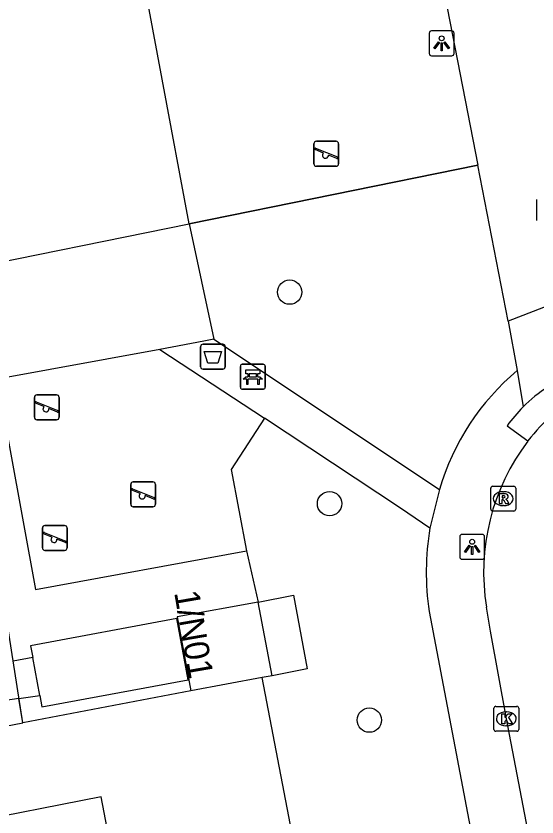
# Model space of a CAD drawing. Extents: x 159265 to 160143, y 383413 to 384319.
# Drawn here: x 159352.88 to 159373.79, y 383756.89 to 383789.05 of the extents above; entities that cross this region are included whole.
import ezdxf

# ---------------------------------------------------------------- set-up
doc = ezdxf.new("R2010")
doc.units = 0
for name, color, linetype in [('IMGEO_Afvalbak', 7, 'Continuous'), ('IMGEO_Bank', 7, 'Continuous'), ('IMGEO_Boom', 7, 'Continuous'), ('IMGEO_Groenvoorziening', 7, 'Continuous'), ('IMGEO_Haag', 7, 'Continuous'), ('IMGEO_Hek', 7, 'Continuous'), ('IMGEO_Kolk', 7, 'Continuous'), ('IMGEO_Lichtpunt', 7, 'Continuous'), ('IMGEO_Pand', 7, 'Continuous'), ('IMGEO_Pand_nummerreeks', 7, 'Continuous'), ('IMGEO_Rijbaan_lokaal_open', 7, 'Continuous'), ('IMGEO_Rioolput', 7, 'Continuous'), ('IMGEO_Speelvoorziening', 7, 'Continuous'), ('IMGEO_Voetpad_open', 7, 'Continuous')]:
    doc.layers.add(name, color=color, linetype=linetype)

msp = doc.modelspace()

# ---------------------------------------------------------------- linework, layer by layer
at = {"layer": 'IMGEO_Afvalbak'}
for p, q in [((159360.284, 383774.97), (159360.284, 383775.77)), ((159360.284, 383775.77), (159360.284, 383774.97)), ((159360.384, 383775.87), (159361.174, 383775.87)), ((159361.174, 383775.87), (159360.384, 383775.87)), ((159361.274, 383775.77), (159361.274, 383774.97)), ((159361.274, 383774.97), (159361.274, 383775.77)), ((159361.174, 383774.87), (159360.384, 383774.87)), ((159360.384, 383774.87), (159361.174, 383774.87))]:
    msp.add_line(p, q, dxfattribs=at)
msp.add_lwpolyline([(159360.427, 383775.584), (159361.131, 383775.584), (159360.982, 383775.114), (159360.576, 383775.114), (159360.427, 383775.584)], dxfattribs=at)
for centre, start, end in [((159360.384, 383775.77), 90, 180), ((159360.384, 383775.77), 90, 180), ((159361.174, 383775.77), 0, 90), ((159361.174, 383775.77), 360, 90), ((159360.384, 383774.97), 180, 270), ((159360.384, 383774.97), 180, 270), ((159361.174, 383774.97), 270, 0), ((159361.174, 383774.97), 270, 0)]:
    msp.add_arc(centre, 0.1, start, end, dxfattribs=at)
at = {"layer": 'IMGEO_Bank'}
for p, q in [((159361.883, 383774.142), (159361.883, 383774.983)), ((159361.883, 383774.983), (159361.883, 383774.142)), ((159361.958, 383775.067), (159362.799, 383775.067)), ((159362.799, 383775.067), (159361.958, 383775.067)), ((159362.883, 383774.992), (159362.883, 383774.151)), ((159362.883, 383774.151), (159362.883, 383774.992)), ((159362.58, 383774.465), (159362.187, 383774.465)), ((159362.192, 383774.573), (159362.192, 383774.679)), ((159362.236, 383774.679), (159362.236, 383774.573)), ((159362.524, 383774.685), (159362.242, 383774.685)), ((159362.242, 383774.567), (159362.524, 383774.567)), ((159362.53, 383774.573), (159362.53, 383774.679)), ((159362.574, 383774.679), (159362.574, 383774.573)), ((159362.808, 383774.067), (159361.967, 383774.067)), ((159361.967, 383774.067), (159362.808, 383774.067))]:
    msp.add_line(p, q, dxfattribs=at)
for points in [[(159362.186, 383774.685), (159362.1, 383774.685), (159362.1, 383774.846), (159362.663, 383774.846), (159362.663, 383774.685), (159362.58, 383774.685)], [(159362.13, 383774.465), (159361.988, 383774.465), (159362.1, 383774.567), (159362.186, 383774.567)], [(159362.18, 383774.458), (159362.18, 383774.251), (159362.137, 383774.251), (159362.137, 383774.458)], [(159362.58, 383774.567), (159362.663, 383774.567), (159362.775, 383774.465), (159362.636, 383774.465)], [(159362.63, 383774.458), (159362.63, 383774.251), (159362.586, 383774.251), (159362.586, 383774.458)]]:
    msp.add_lwpolyline(points, dxfattribs=at)
for centre, radius, start, end in [((159361.961, 383774.989), 0.0779, 92.4484, 184.2845), ((159361.961, 383774.989), 0.0779, 92.4484, 184.2845), ((159362.805, 383774.989), 0.0779, 2.4484, 94.2845), ((159362.805, 383774.989), 0.0779, 2.4484, 94.2845), ((159362.13, 383774.458), 0.00671, 2.8957, 87.1043), ((159362.187, 383774.458), 0.00671, 92.8957, 177.1043), ((159362.185, 383774.678), 0.00671, 2.8957, 87.1043), ((159362.185, 383774.574), 0.00671, 272.8957, 357.1043), ((159362.242, 383774.678), 0.00671, 92.8957, 177.1043), ((159362.242, 383774.574), 0.00671, 182.8957, 267.1043), ((159362.524, 383774.678), 0.00671, 2.8957, 87.1043), ((159362.524, 383774.574), 0.00671, 272.8957, 357.1043), ((159362.581, 383774.678), 0.00671, 92.8957, 177.1043), ((159362.581, 383774.574), 0.00671, 182.8957, 267.1043), ((159362.579, 383774.458), 0.00671, 2.8957, 87.1043), ((159362.636, 383774.458), 0.00671, 92.8957, 177.1043), ((159361.961, 383774.145), 0.0779, 182.4484, 274.2845), ((159361.961, 383774.145), 0.0779, 182.4484, 274.2845), ((159362.805, 383774.145), 0.0779, 272.4484, 4.2845), ((159362.805, 383774.145), 0.0779, 272.4484, 4.2845)]:
    msp.add_arc(centre, radius, start, end, dxfattribs=at)
at = {"layer": 'IMGEO_Boom'}
for centre in [(159363.859, 383777.962), (159365.461, 383769.471), (159367.059, 383760.78)]:
    msp.add_circle(centre, 0.489, dxfattribs=at)
at = {"layer": 'IMGEO_Groenvoorziening'}
for points in [[(159371.407, 383783.066), (159359.832, 383780.702)], [(159359.832, 383780.702), (159360.811, 383776.068)], [(159358.645, 383775.662), (159352.106, 383774.47), (159353.662, 383766.028), (159362.132, 383767.578)], [(159362.851, 383772.897), (159361.511, 383770.836), (159362.132, 383767.578)], [(159362.132, 383767.578), (159362.599, 383765.517)], [(159368.719, 383731.446), (159365.154, 383750), (159362.754, 383762.488)], [(159359.896, 383761.959), (159353.148, 383760.666)]]:
    msp.add_lwpolyline(points, dxfattribs=at)
at = {"layer": 'IMGEO_Haag'}
for points in [[(159353.148, 383760.666), (159352.995, 383761.644)], [(159333.621, 383756.912), (159353.148, 383760.666)]]:
    msp.add_lwpolyline(points, dxfattribs=at)
at = {"layer": 'IMGEO_Hek'}
for points in [[(159359.832, 383780.702), (159354.405, 383809.755)], [(159359.832, 383780.702), (159371.407, 383783.066)], [(159350.482, 383777.746), (159350.322, 383778.775), (159359.832, 383780.702)], [(159353.148, 383760.666), (159350.482, 383777.746)], [(159359.896, 383761.959), (159353.148, 383760.666)]]:
    msp.add_lwpolyline(points, dxfattribs=at)
at = {"layer": 'IMGEO_Kolk'}
for p, q in [((159373.785, 383780.835), (159373.785, 383781.687)), ((159372.055, 383760.407), (159372.055, 383761.259)), ((159372.13, 383761.333), (159372.982, 383761.333)), ((159373.056, 383761.259), (159373.056, 383760.407)), ((159372.543, 383761.113), (159372.568, 383761.113)), ((159372.982, 383760.333), (159372.13, 383760.333)), ((159372.566, 383760.553), (159372.541, 383760.553))]:
    msp.add_line(p, q, dxfattribs=at)
for points in [[(159373.785, 383780.835), (159373.785, 383781.687)], [(159372.055, 383760.407), (159372.055, 383761.259)], [(159372.13, 383761.333), (159372.982, 383761.333)], [(159373.056, 383761.259), (159373.056, 383760.407)], [(159372.376, 383761.033), (159372.499, 383761.033), (159372.499, 383760.882), (159372.629, 383761.033), (159372.793, 383761.033), (159372.647, 383760.882), (159372.8, 383760.633), (159372.648, 383760.633), (159372.563, 383760.797), (159372.499, 383760.73), (159372.499, 383760.633), (159372.376, 383760.633), (159372.376, 383761.033)], [(159372.982, 383760.333), (159372.13, 383760.333)]]:
    msp.add_lwpolyline(points, dxfattribs=at)
for centre, start, end in [((159372.132, 383761.257), 91.552, 178.448), ((159372.132, 383761.257), 91.552, 178.448), ((159372.98, 383761.257), 1.552, 88.448), ((159372.98, 383761.257), 1.552, 88.448), ((159372.132, 383760.409), 181.552, 268.448), ((159372.132, 383760.409), 181.552, 268.448), ((159372.98, 383760.409), 271.552, 358.448), ((159372.98, 383760.409), 271.552, 358.448)]:
    msp.add_arc(centre, 0.0765, start, end, dxfattribs=at)
for centre, major_axis, ratio, start_param, end_param in [((159372.542, 383760.833), (-0.387, 0.002), 0.722429, 4.712389, 7.853982), ((159372.567, 383760.833), (-0.39, 0.002), 0.717154, 1.570796, 4.712389)]:
    msp.add_ellipse(centre, major_axis=major_axis, ratio=ratio, start_param=start_param, end_param=end_param, dxfattribs=at)
at = {"layer": 'IMGEO_Lichtpunt'}
for p, q in [((159369.461, 383788.354), (159369.461, 383787.547)), ((159369.461, 383788.354), (159369.461, 383787.547)), ((159370.363, 383788.449), (159369.555, 383788.449)), ((159370.363, 383788.449), (159369.555, 383788.449)), ((159370.457, 383787.547), (159370.457, 383788.354)), ((159370.457, 383787.547), (159370.457, 383788.354)), ((159369.555, 383787.453), (159370.363, 383787.453)), ((159369.555, 383787.453), (159370.363, 383787.453)), ((159370.686, 383768.141), (159370.686, 383767.334)), ((159370.686, 383768.141), (159370.686, 383767.334)), ((159371.588, 383768.236), (159370.78, 383768.236)), ((159371.588, 383768.236), (159370.78, 383768.236)), ((159371.682, 383767.334), (159371.682, 383768.141)), ((159371.682, 383767.334), (159371.682, 383768.141)), ((159370.78, 383767.24), (159371.588, 383767.24)), ((159370.78, 383767.24), (159371.588, 383767.24))]:
    msp.add_line(p, q, dxfattribs=at)
for points in [[(159369.835, 383788.018), (159369.874, 383787.99), (159369.686, 383787.728), (159369.648, 383787.755), (159369.835, 383788.018)], [(159369.937, 383787.97), (159369.984, 383787.97), (159369.984, 383787.648), (159369.937, 383787.648), (159369.937, 383787.97)], [(159370.047, 383787.99), (159370.085, 383788.017), (159370.272, 383787.755), (159370.233, 383787.727), (159370.047, 383787.99)], [(159371.06, 383767.805), (159371.099, 383767.777), (159370.911, 383767.515), (159370.873, 383767.542), (159371.06, 383767.805)], [(159371.162, 383767.757), (159371.209, 383767.757), (159371.209, 383767.435), (159371.162, 383767.435), (159371.162, 383767.757)], [(159371.272, 383767.777), (159371.31, 383767.804), (159371.497, 383767.542), (159371.458, 383767.514), (159371.272, 383767.777)]]:
    msp.add_lwpolyline(points, dxfattribs=at)
for centre in [(159369.96, 383788.152), (159371.185, 383767.939)]:
    msp.add_circle(centre, 0.0994, dxfattribs=at)
for centre, start, end in [((159369.555, 383788.354), 90, 180), ((159369.555, 383788.354), 90, 180), ((159370.363, 383788.354), 0, 90), ((159370.363, 383788.354), 0, 90), ((159369.555, 383787.547), 180, 270), ((159369.555, 383787.547), 180, 270), ((159370.363, 383787.547), 270, 0), ((159370.363, 383787.547), 270, 360), ((159370.78, 383768.141), 90, 180), ((159370.78, 383768.141), 90, 180), ((159371.588, 383768.141), 0, 90), ((159371.588, 383768.141), 0, 90), ((159370.78, 383767.334), 180, 270), ((159370.78, 383767.334), 180, 270), ((159371.588, 383767.334), 270, 0), ((159371.588, 383767.334), 270, 360)]:
    msp.add_arc(centre, 0.0946, start, end, dxfattribs=at)
at = {"layer": 'IMGEO_Pand'}
for points in [[(159362.599, 383765.517), (159359.341, 383764.922), (159359.896, 383761.959)], [(159363.152, 383762.562), (159362.599, 383765.517)], [(159353.832, 383761.767), (159353.917, 383761.309), (159359.789, 383762.399), (159359.333, 383764.857), (159353.461, 383763.767), (159353.55, 383763.288)], [(159353.832, 383761.767), (159353.55, 383763.288)], [(159363.152, 383762.562), (159362.754, 383762.488)], [(159362.754, 383762.488), (159359.896, 383761.959)], [(159344.704, 383730.975), (159345.759, 383725.591), (159354.54, 383727.272), (159361.423, 383728.589), (159361.846, 383728.67), (159357.766, 383750), (159356.294, 383757.697), (159350.703, 383756.598), (159341.398, 383754.835), (159342.325, 383750), (159344.839, 383736.882), (159345.562, 383733.106), (159345.686, 383732.457)]]:
    msp.add_lwpolyline(points, dxfattribs=at)
at = {"layer": 'IMGEO_Rijbaan_lokaal_open'}
for points in [[(159359.832, 383780.702), (159354.405, 383809.755)], [(159369.337, 383805.354), (159367.228, 383804.567), (159371.407, 383783.066)], [(159372.625, 383776.797), (159371.407, 383783.066)], [(159376.917, 383780.881), (159377.366, 383778.632), (159372.625, 383776.797)], [(159350.482, 383777.746), (159350.322, 383778.775), (159359.832, 383780.702)], [(159379.171, 383727.071), (159378.426, 383730.192), (159378.274, 383730.973), (159377.881, 383732.974), (159375.788, 383743.999), (159374.636, 383750), (159372.557, 383760.833), (159371.919, 383764.35), (159371.76, 383765.311)]]:
    msp.add_lwpolyline(points, dxfattribs=at)
for centre, radius, start, end in [((159377.845, 383768.747), 5.48, 112.7814, 143.7617), ((159380.327, 383766.719), 8.682, 142.6526, 189.3355)]:
    msp.add_arc(centre, radius, start, end, dxfattribs=at)
at = {"layer": 'IMGEO_Rioolput'}
for p, q in [((159371.931, 383769.245), (159371.931, 383770.097)), ((159372.006, 383770.171), (159372.858, 383770.171)), ((159372.419, 383769.951), (159372.444, 383769.951)), ((159372.932, 383770.097), (159372.932, 383769.245)), ((159372.442, 383769.391), (159372.417, 383769.391)), ((159372.858, 383769.171), (159372.006, 383769.171))]:
    msp.add_line(p, q, dxfattribs=at)
for points in [[(159371.931, 383769.245), (159371.931, 383770.097)], [(159372.006, 383770.171), (159372.858, 383770.171)], [(159372.932, 383770.097), (159372.932, 383769.245)], [(159372.52, 383769.869), (159372.268, 383769.871), (159372.268, 383769.471)], [(159372.268, 383769.471), (159372.392, 383769.471), (159372.392, 383769.633), (159372.403, 383769.633)], [(159372.446, 383769.79), (159372.392, 383769.79), (159372.392, 383769.709)], [(159372.392, 383769.709), (159372.444, 383769.709)], [(159372.45, 383769.604), (159372.521, 383769.471), (159372.661, 383769.471), (159372.596, 383769.597)], [(159372.858, 383769.171), (159372.006, 383769.171)]]:
    msp.add_lwpolyline(points, dxfattribs=at)
for centre, radius, start, end in [((159372.008, 383770.095), 0.0765, 91.552, 178.448), ((159372.008, 383770.095), 0.0765, 91.552, 178.448), ((159372.856, 383770.095), 0.0765, 1.552, 88.448), ((159372.856, 383770.095), 0.0765, 1.552, 88.448), ((159372.402, 383769.58), 0.0533, 26.0293, 88.6989), ((159372.428, 383769.898), 0.19, 274.7715, 282.9687), ((159372.452, 383769.694), 0.0964, 77.0061, 93.1865), ((159372.466, 383769.751), 0.0378, 276.6634, 79.6772), ((159372.519, 383769.759), 0.109, 350.3612, 89.416), ((159372.517, 383769.759), 0.112, 277.5842, 350.9817), ((159372.501, 383769.544), 0.108, 29.5134, 73.7905), ((159372.008, 383769.247), 0.0765, 181.552, 268.448), ((159372.008, 383769.247), 0.0765, 181.552, 268.448), ((159372.856, 383769.247), 0.0765, 271.552, 358.448), ((159372.856, 383769.247), 0.0765, 271.552, 358.448)]:
    msp.add_arc(centre, radius, start, end, dxfattribs=at)
for centre, major_axis, ratio, start_param, end_param in [((159372.418, 383769.671), (-0.387, 0.002), 0.722429, 4.712389, 7.853982), ((159372.443, 383769.671), (-0.39, 0.002), 0.717154, 1.570796, 4.712389)]:
    msp.add_ellipse(centre, major_axis=major_axis, ratio=ratio, start_param=start_param, end_param=end_param, dxfattribs=at)
at = {"layer": 'IMGEO_Speelvoorziening'}
for p, q in [((159364.834, 383783.118), (159364.834, 383783.918)), ((159364.834, 383783.918), (159364.834, 383783.118)), ((159364.934, 383784.018), (159365.724, 383784.018)), ((159365.724, 383784.018), (159364.934, 383784.018)), ((159365.824, 383783.918), (159365.824, 383783.118)), ((159365.824, 383783.118), (159365.824, 383783.918)), ((159365.217, 383783.546), (159364.878, 383783.683)), ((159364.903, 383783.743), (159365.779, 383783.39)), ((159365.755, 383783.33), (159365.415, 383783.467)), ((159365.724, 383783.018), (159364.934, 383783.018)), ((159364.934, 383783.018), (159365.724, 383783.018)), ((159353.717, 383773.838), (159354.507, 383773.838)), ((159354.507, 383773.838), (159353.717, 383773.838)), ((159353.617, 383772.938), (159353.617, 383773.738)), ((159353.617, 383773.738), (159353.617, 383772.938)), ((159354, 383773.366), (159353.661, 383773.503)), ((159353.686, 383773.563), (159354.562, 383773.21)), ((159354.607, 383773.738), (159354.607, 383772.938)), ((159354.607, 383772.938), (159354.607, 383773.738)), ((159354.538, 383773.15), (159354.198, 383773.287)), ((159354.507, 383772.838), (159353.717, 383772.838)), ((159353.717, 383772.838), (159354.507, 383772.838)), ((159357.582, 383770.344), (159358.372, 383770.344)), ((159358.372, 383770.344), (159357.582, 383770.344)), ((159357.482, 383769.444), (159357.482, 383770.244)), ((159357.482, 383770.244), (159357.482, 383769.444)), ((159357.865, 383769.872), (159357.526, 383770.009)), ((159357.551, 383770.069), (159358.427, 383769.716)), ((159358.472, 383770.244), (159358.472, 383769.444)), ((159358.472, 383769.444), (159358.472, 383770.244)), ((159358.403, 383769.656), (159358.063, 383769.793)), ((159358.372, 383769.344), (159357.582, 383769.344)), ((159357.582, 383769.344), (159358.372, 383769.344)), ((159353.938, 383767.694), (159353.938, 383768.494)), ((159353.938, 383768.494), (159353.938, 383767.694)), ((159354.038, 383768.594), (159354.828, 383768.594)), ((159354.828, 383768.594), (159354.038, 383768.594)), ((159354.928, 383768.494), (159354.928, 383767.694)), ((159354.928, 383767.694), (159354.928, 383768.494)), ((159354.321, 383768.122), (159353.982, 383768.259)), ((159354.007, 383768.319), (159354.883, 383767.966)), ((159354.859, 383767.906), (159354.519, 383768.043)), ((159354.828, 383767.594), (159354.038, 383767.594)), ((159354.038, 383767.594), (159354.828, 383767.594))]:
    msp.add_line(p, q, dxfattribs=at)
for centre, radius, start, end in [((159364.934, 383783.918), 0.1, 90, 180), ((159364.934, 383783.918), 0.1, 90, 180), ((159365.724, 383783.918), 0.1, 0, 90), ((159365.724, 383783.918), 0.1, 360, 90), ((159364.891, 383783.713), 0.0327, 68.078, 248.078), ((159365.296, 383783.456), 0.12, 130.9928, 5.1632), ((159365.767, 383783.36), 0.0327, 248.078, 68.078), ((159364.934, 383783.118), 0.1, 180, 270), ((159364.934, 383783.118), 0.1, 180, 270), ((159365.724, 383783.118), 0.1, 270, 0), ((159365.724, 383783.118), 0.1, 270, 0), ((159353.717, 383773.738), 0.1, 90, 180), ((159353.717, 383773.738), 0.1, 90, 180), ((159354.507, 383773.738), 0.1, 0, 90), ((159354.507, 383773.738), 0.1, 360, 90), ((159353.674, 383773.533), 0.0327, 68.078, 248.078), ((159354.079, 383773.276), 0.12, 130.9928, 5.1632), ((159354.55, 383773.18), 0.0327, 248.078, 68.078), ((159353.717, 383772.938), 0.1, 180, 270), ((159353.717, 383772.938), 0.1, 180, 270), ((159354.507, 383772.938), 0.1, 270, 0), ((159354.507, 383772.938), 0.1, 270, 0), ((159357.582, 383770.244), 0.1, 90, 180), ((159357.582, 383770.244), 0.1, 90, 180), ((159358.372, 383770.244), 0.1, 0, 90), ((159358.372, 383770.244), 0.1, 360, 90), ((159357.539, 383770.039), 0.0327, 68.078, 248.078), ((159357.944, 383769.782), 0.12, 130.9928, 5.1632), ((159358.415, 383769.686), 0.0327, 248.078, 68.078), ((159357.582, 383769.444), 0.1, 180, 270), ((159357.582, 383769.444), 0.1, 180, 270), ((159358.372, 383769.444), 0.1, 270, 0), ((159358.372, 383769.444), 0.1, 270, 0), ((159354.038, 383768.494), 0.1, 90, 180), ((159354.038, 383768.494), 0.1, 90, 180), ((159354.828, 383768.494), 0.1, 0, 90), ((159354.828, 383768.494), 0.1, 360, 90), ((159353.995, 383768.289), 0.0327, 68.078, 248.078), ((159354.4, 383768.032), 0.12, 130.9928, 5.1632), ((159354.038, 383767.694), 0.1, 180, 270), ((159354.038, 383767.694), 0.1, 180, 270), ((159354.828, 383767.694), 0.1, 270, 0), ((159354.828, 383767.694), 0.1, 270, 0), ((159354.871, 383767.936), 0.0327, 248.078, 68.078)]:
    msp.add_arc(centre, radius, start, end, dxfattribs=at)
at = {"layer": 'IMGEO_Voetpad_open'}
for points in [[(159372.625, 383776.797), (159372.993, 383774.817)], [(159360.811, 383776.068), (159360.42, 383775.995), (159358.645, 383775.662)], [(159360.811, 383776.068), (159369.87, 383770.038)], [(159358.645, 383775.662), (159362.851, 383772.897)], [(159372.993, 383774.817), (159373.23, 383773.352)], [(159369.491, 383768.488), (159368.305, 383769.288), (159362.851, 383772.897)], [(159372.586, 383772.601), (159373.425, 383771.986)], [(159369.87, 383770.038), (159369.491, 383768.488)], [(159362.599, 383765.517), (159364.014, 383765.794), (159364.565, 383762.838), (159363.152, 383762.562)], [(159369.458, 383765.136), (159372.341, 383750), (159375.895, 383731.337), (159376.664, 383727.861)], [(159353.55, 383763.288), (159352.761, 383763.148)], [(159352.995, 383761.644), (159351.981, 383761.496)], [(159352.995, 383761.644), (159353.832, 383761.767)]]:
    msp.add_lwpolyline(points, dxfattribs=at)
for centre, radius, start, end in [((159379.38, 383767.233), 9.915, 130.1037, 163.5683), ((159377.833, 383768.762), 6.501, 112.5453, 135.085), ((159377.85, 383768.738), 6.529, 135.0412, 143.731), ((159379.929, 383766.709), 10.588, 170.3277, 188.5442)]:
    msp.add_arc(centre, radius, start, end, dxfattribs=at)

# ---------------------------------------------------------------- texts
at = {"layer": 'IMGEO_Pand_nummerreeks'}
msp.add_text('1/N01', height=1, rotation=279.7824, dxfattribs=at).set_placement((159359.223, 383765.905))

doc.saveas('drawing.dxf')
